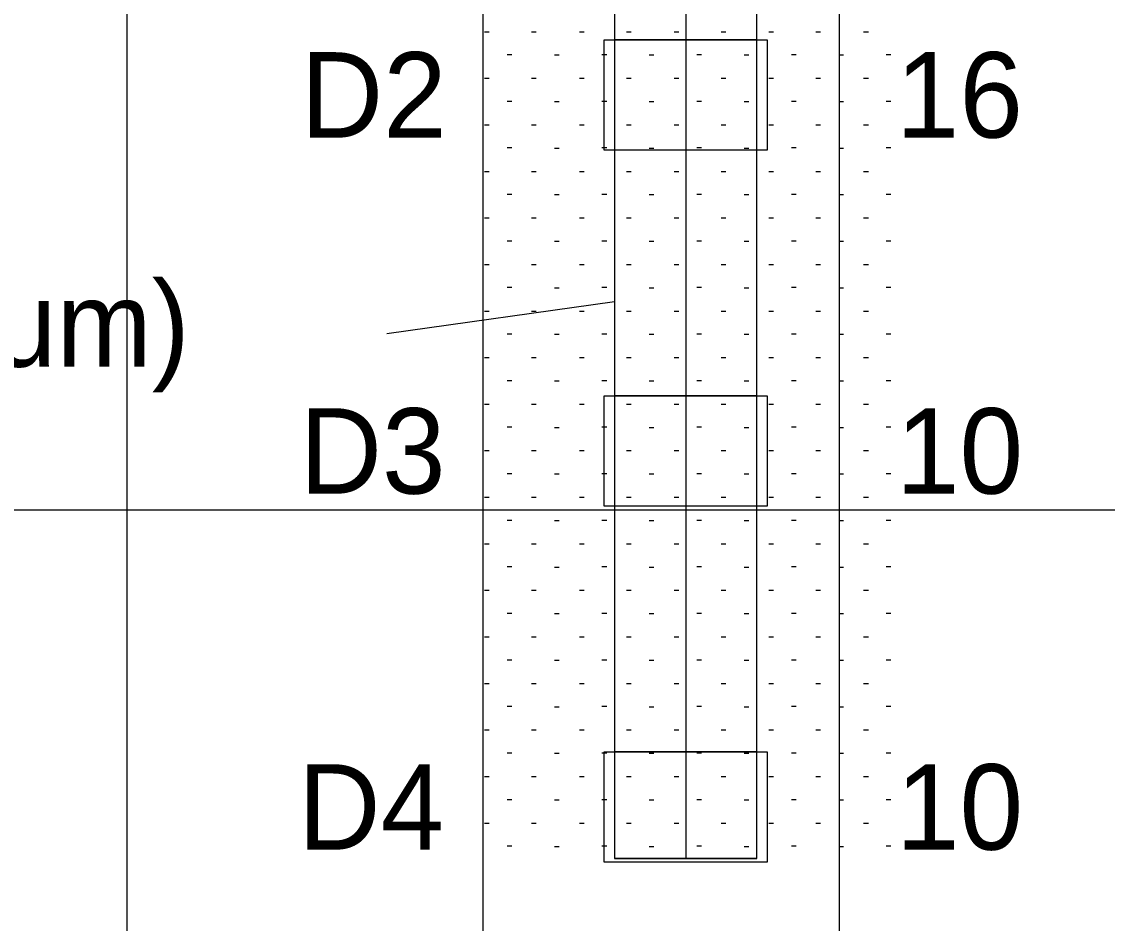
# Model space of a CAD drawing. Extents: x -290 to 297, y 616 to 861.
# Drawn here: x 137.04 to 167.52, y 678.38 to 703.71 of the extents above; entities that cross this region are included whole.
import ezdxf

# ---------------------------------------------------------------- set-up
doc = ezdxf.new("R2010")
doc.units = 0
for name, color, linetype in [('Default', 7, 'Continuous'), ('DisROW Proposed Temp Easements', 7, 'Continuous'), ('Draft_4', 7, 'Continuous'), ('SewerStormPipe', 7, 'Continuous'), ('TextAlignment', 7, 'Continuous'), ('TextAlignmentSml', 7, 'Continuous'), ('V-SWLK-CONC', 7, 'Continuous')]:
    doc.layers.add(name, color=color, linetype=linetype)

msp = doc.modelspace()

# ---------------------------------------------------------------- linework, layer by layer
at = {"layer": 'Default'}
for p, q in [((155.685, 741.2), (155.685, 680.2)), ((157.685, 680.2), (153.685, 680.2))]:
    msp.add_line(p, q, dxfattribs=at)
at = {"layer": 'DisROW Proposed Temp Easements'}
for points in [[(153.397, 703.2), (157.973, 703.2), (157.973, 700.104), (153.397, 700.104)], [(153.397, 693.2), (157.973, 693.2), (157.973, 690.104), (153.397, 690.104)], [(153.397, 683.2), (157.973, 683.2), (157.973, 680.104), (153.397, 680.104)]]:
    msp.add_lwpolyline(points, close=True, dxfattribs=at)
at = {"layer": 'Draft_4'}
msp.add_lwpolyline([(157.685, 717.2), (153.685, 717.2), (153.685, 680.2), (157.685, 680.2)], close=True, dxfattribs=at)
at = {"layer": 'SewerStormPipe'}
for p, q in [((157.685, 703.2), (153.685, 703.2)), ((157.685, 693.2), (153.685, 693.2)), ((157.685, 683.2), (153.685, 683.2))]:
    msp.add_line(p, q, dxfattribs=at)
at = {"layer": 'TextAlignment'}
for p, q in [((140, 630), (140, 787.989)), ((160, 630), (160, 787.989)), ((-275.612, 690), (284.208, 690))]:
    msp.add_line(p, q, dxfattribs=at)
at = {"layer": 'TextAlignmentSml'}
msp.add_line((150, 630), (150, 787.989), dxfattribs=at)
at = {"layer": 'V-SWLK-CONC'}
for p, q in [((150.038, 703.426), (150.17, 703.426)), ((151.358, 703.426), (151.49, 703.426)), ((152.699, 703.426), (152.831, 703.426)), ((154.019, 703.426), (154.151, 703.426)), ((155.36, 703.426), (155.492, 703.426)), ((156.68, 703.426), (156.812, 703.426)), ((158.021, 703.426), (158.153, 703.426)), ((159.341, 703.426), (159.473, 703.426)), ((160.682, 703.426), (160.814, 703.426)), ((150.673, 702.786), (150.805, 702.786)), ((152.002, 702.773), (152.134, 702.773)), ((153.334, 702.786), (153.466, 702.786)), ((154.663, 702.773), (154.795, 702.773)), ((155.995, 702.786), (156.127, 702.786)), ((157.324, 702.773), (157.456, 702.773)), ((158.656, 702.786), (158.788, 702.786)), ((159.985, 702.773), (160.117, 702.773)), ((161.317, 702.786), (161.449, 702.786)), ((150.038, 702.119), (150.17, 702.119)), ((151.358, 702.119), (151.49, 702.119)), ((152.699, 702.119), (152.831, 702.119)), ((154.019, 702.119), (154.151, 702.119)), ((155.36, 702.119), (155.492, 702.119)), ((156.68, 702.119), (156.812, 702.119)), ((158.021, 702.119), (158.153, 702.119)), ((159.341, 702.119), (159.473, 702.119)), ((160.682, 702.119), (160.814, 702.119)), ((150.673, 701.478), (150.805, 701.478)), ((152.002, 701.465), (152.134, 701.465)), ((153.334, 701.478), (153.466, 701.478)), ((154.663, 701.465), (154.795, 701.465)), ((155.995, 701.478), (156.127, 701.478)), ((157.324, 701.465), (157.456, 701.465)), ((158.656, 701.478), (158.788, 701.478)), ((159.985, 701.465), (160.117, 701.465)), ((161.317, 701.478), (161.449, 701.478)), ((150.038, 700.811), (150.17, 700.811)), ((151.358, 700.811), (151.49, 700.811)), ((152.699, 700.811), (152.831, 700.811)), ((154.019, 700.811), (154.151, 700.811)), ((155.36, 700.811), (155.492, 700.811)), ((156.68, 700.811), (156.812, 700.811)), ((158.021, 700.811), (158.153, 700.811)), ((159.341, 700.811), (159.473, 700.811)), ((160.682, 700.811), (160.814, 700.811)), ((150.673, 700.171), (150.805, 700.171)), ((152.002, 700.157), (152.134, 700.157)), ((153.334, 700.171), (153.466, 700.171)), ((154.663, 700.157), (154.795, 700.157)), ((155.995, 700.171), (156.127, 700.171)), ((157.324, 700.157), (157.456, 700.157)), ((158.656, 700.171), (158.788, 700.171)), ((159.985, 700.157), (160.117, 700.157)), ((161.317, 700.171), (161.449, 700.171)), ((150.038, 699.504), (150.17, 699.504)), ((151.358, 699.504), (151.49, 699.504)), ((152.699, 699.504), (152.831, 699.504)), ((154.019, 699.504), (154.151, 699.504)), ((155.36, 699.504), (155.492, 699.504)), ((156.68, 699.504), (156.812, 699.504)), ((158.021, 699.504), (158.153, 699.504)), ((159.341, 699.504), (159.473, 699.504)), ((160.682, 699.504), (160.814, 699.504)), ((150.673, 698.863), (150.805, 698.863)), ((152.002, 698.85), (152.134, 698.85)), ((153.334, 698.863), (153.466, 698.863)), ((154.663, 698.85), (154.795, 698.85)), ((155.995, 698.863), (156.127, 698.863)), ((157.324, 698.85), (157.456, 698.85)), ((158.656, 698.863), (158.788, 698.863)), ((159.985, 698.85), (160.117, 698.85)), ((161.317, 698.863), (161.449, 698.863)), ((150.038, 698.196), (150.17, 698.196)), ((151.358, 698.196), (151.49, 698.196)), ((152.699, 698.196), (152.831, 698.196)), ((154.019, 698.196), (154.151, 698.196)), ((155.36, 698.196), (155.492, 698.196)), ((156.68, 698.196), (156.812, 698.196)), ((158.021, 698.196), (158.153, 698.196)), ((159.341, 698.196), (159.473, 698.196)), ((160.682, 698.196), (160.814, 698.196)), ((150.673, 697.556), (150.805, 697.556)), ((152.002, 697.542), (152.134, 697.542)), ((153.334, 697.556), (153.466, 697.556)), ((154.663, 697.542), (154.795, 697.542)), ((155.995, 697.556), (156.127, 697.556)), ((157.324, 697.542), (157.456, 697.542)), ((158.656, 697.556), (158.788, 697.556)), ((159.985, 697.542), (160.117, 697.542)), ((161.317, 697.556), (161.449, 697.556)), ((150.038, 696.889), (150.17, 696.889)), ((151.358, 696.889), (151.49, 696.889)), ((152.699, 696.889), (152.831, 696.889)), ((154.019, 696.889), (154.151, 696.889)), ((155.36, 696.889), (155.492, 696.889)), ((156.68, 696.889), (156.812, 696.889)), ((158.021, 696.889), (158.153, 696.889)), ((159.341, 696.889), (159.473, 696.889)), ((160.682, 696.889), (160.814, 696.889)), ((150.673, 696.248), (150.805, 696.248)), ((152.002, 696.235), (152.134, 696.235)), ((153.334, 696.248), (153.466, 696.248)), ((154.663, 696.235), (154.795, 696.235)), ((155.995, 696.248), (156.127, 696.248)), ((157.324, 696.235), (157.456, 696.235)), ((158.656, 696.248), (158.788, 696.248)), ((159.985, 696.235), (160.117, 696.235)), ((161.317, 696.248), (161.449, 696.248)), ((153.685, 695.838), (147.295, 694.94)), ((150.038, 695.581), (150.17, 695.581)), ((151.358, 695.581), (151.49, 695.581)), ((152.699, 695.581), (152.831, 695.581)), ((154.019, 695.581), (154.151, 695.581)), ((155.36, 695.581), (155.492, 695.581)), ((156.68, 695.581), (156.812, 695.581)), ((158.021, 695.581), (158.153, 695.581)), ((159.341, 695.581), (159.473, 695.581)), ((160.682, 695.581), (160.814, 695.581)), ((150.673, 694.941), (150.805, 694.941)), ((152.002, 694.927), (152.134, 694.927)), ((153.334, 694.941), (153.466, 694.941)), ((154.663, 694.927), (154.795, 694.927)), ((155.995, 694.941), (156.127, 694.941)), ((157.324, 694.927), (157.456, 694.927)), ((158.656, 694.941), (158.788, 694.941)), ((159.985, 694.927), (160.117, 694.927)), ((161.317, 694.941), (161.449, 694.941)), ((150.038, 694.274), (150.17, 694.274)), ((151.358, 694.274), (151.49, 694.274)), ((152.699, 694.274), (152.831, 694.274)), ((154.019, 694.274), (154.151, 694.274)), ((155.36, 694.274), (155.492, 694.274)), ((156.68, 694.274), (156.812, 694.274)), ((158.021, 694.274), (158.153, 694.274)), ((159.341, 694.274), (159.473, 694.274)), ((160.682, 694.274), (160.814, 694.274)), ((150.673, 693.633), (150.805, 693.633)), ((152.002, 693.62), (152.134, 693.62)), ((153.334, 693.633), (153.466, 693.633)), ((154.663, 693.62), (154.795, 693.62)), ((155.995, 693.633), (156.127, 693.633)), ((157.324, 693.62), (157.456, 693.62)), ((158.656, 693.633), (158.788, 693.633)), ((159.985, 693.62), (160.117, 693.62)), ((161.317, 693.633), (161.449, 693.633)), ((150.038, 692.966), (150.17, 692.966)), ((151.358, 692.966), (151.49, 692.966)), ((152.699, 692.966), (152.831, 692.966)), ((154.019, 692.966), (154.151, 692.966)), ((155.36, 692.966), (155.492, 692.966)), ((156.68, 692.966), (156.812, 692.966)), ((158.021, 692.966), (158.153, 692.966)), ((159.341, 692.966), (159.473, 692.966)), ((160.682, 692.966), (160.814, 692.966)), ((150.673, 692.326), (150.805, 692.326)), ((152.002, 692.312), (152.134, 692.312)), ((153.334, 692.326), (153.466, 692.326)), ((154.663, 692.312), (154.795, 692.312)), ((155.995, 692.326), (156.127, 692.326)), ((157.324, 692.312), (157.456, 692.312)), ((158.656, 692.326), (158.788, 692.326)), ((159.985, 692.312), (160.117, 692.312)), ((161.317, 692.326), (161.449, 692.326)), ((150.038, 691.659), (150.17, 691.659)), ((151.358, 691.659), (151.49, 691.659)), ((152.699, 691.659), (152.831, 691.659)), ((154.019, 691.659), (154.151, 691.659)), ((155.36, 691.659), (155.492, 691.659)), ((156.68, 691.659), (156.812, 691.659)), ((158.021, 691.659), (158.153, 691.659)), ((159.341, 691.659), (159.473, 691.659)), ((160.682, 691.659), (160.814, 691.659)), ((150.673, 691.018), (150.805, 691.018)), ((152.002, 691.005), (152.134, 691.005)), ((153.334, 691.018), (153.466, 691.018)), ((154.663, 691.005), (154.795, 691.005)), ((155.995, 691.018), (156.127, 691.018)), ((157.324, 691.005), (157.456, 691.005)), ((158.656, 691.018), (158.788, 691.018)), ((159.985, 691.005), (160.117, 691.005)), ((161.317, 691.018), (161.449, 691.018)), ((150.038, 690.351), (150.17, 690.351)), ((151.358, 690.351), (151.49, 690.351)), ((152.699, 690.351), (152.831, 690.351)), ((154.019, 690.351), (154.151, 690.351)), ((155.36, 690.351), (155.492, 690.351)), ((156.68, 690.351), (156.812, 690.351)), ((158.021, 690.351), (158.153, 690.351)), ((159.341, 690.351), (159.473, 690.351)), ((160.682, 690.351), (160.814, 690.351)), ((150.673, 689.71), (150.805, 689.71)), ((152.002, 689.697), (152.134, 689.697)), ((153.334, 689.71), (153.466, 689.71)), ((154.663, 689.697), (154.795, 689.697)), ((155.995, 689.71), (156.127, 689.71)), ((157.324, 689.697), (157.456, 689.697)), ((158.656, 689.71), (158.788, 689.71)), ((159.985, 689.697), (160.117, 689.697)), ((161.317, 689.71), (161.449, 689.71)), ((150.038, 689.043), (150.17, 689.043)), ((151.358, 689.043), (151.49, 689.043)), ((152.699, 689.043), (152.831, 689.043)), ((154.019, 689.043), (154.151, 689.043)), ((155.36, 689.043), (155.492, 689.043)), ((156.68, 689.043), (156.812, 689.043)), ((158.021, 689.043), (158.153, 689.043)), ((159.341, 689.043), (159.473, 689.043)), ((160.682, 689.043), (160.814, 689.043)), ((150.673, 688.403), (150.805, 688.403)), ((152.002, 688.39), (152.134, 688.39)), ((153.334, 688.403), (153.466, 688.403)), ((154.663, 688.39), (154.795, 688.39)), ((155.995, 688.403), (156.127, 688.403)), ((157.324, 688.39), (157.456, 688.39)), ((158.656, 688.403), (158.788, 688.403)), ((159.985, 688.39), (160.117, 688.39)), ((161.317, 688.403), (161.449, 688.403)), ((150.038, 687.736), (150.17, 687.736)), ((151.358, 687.736), (151.49, 687.736)), ((152.699, 687.736), (152.831, 687.736)), ((154.019, 687.736), (154.151, 687.736)), ((155.36, 687.736), (155.492, 687.736)), ((156.68, 687.736), (156.812, 687.736)), ((158.021, 687.736), (158.153, 687.736)), ((159.341, 687.736), (159.473, 687.736)), ((160.682, 687.736), (160.814, 687.736)), ((150.673, 687.095), (150.805, 687.095)), ((152.002, 687.082), (152.134, 687.082)), ((153.334, 687.095), (153.466, 687.095)), ((154.663, 687.082), (154.795, 687.082)), ((155.995, 687.095), (156.127, 687.095)), ((157.324, 687.082), (157.456, 687.082)), ((158.656, 687.095), (158.788, 687.095)), ((159.985, 687.082), (160.117, 687.082)), ((161.317, 687.095), (161.449, 687.095)), ((150.038, 686.428), (150.17, 686.428)), ((151.358, 686.428), (151.49, 686.428)), ((152.699, 686.428), (152.831, 686.428)), ((154.019, 686.428), (154.151, 686.428)), ((155.36, 686.428), (155.492, 686.428)), ((156.68, 686.428), (156.812, 686.428)), ((158.021, 686.428), (158.153, 686.428)), ((159.341, 686.428), (159.473, 686.428)), ((160.682, 686.428), (160.814, 686.428)), ((150.673, 685.788), (150.805, 685.788)), ((152.002, 685.775), (152.134, 685.775)), ((153.334, 685.788), (153.466, 685.788)), ((154.663, 685.775), (154.795, 685.775)), ((155.995, 685.788), (156.127, 685.788)), ((157.324, 685.775), (157.456, 685.775)), ((158.656, 685.788), (158.788, 685.788)), ((159.985, 685.775), (160.117, 685.775)), ((161.317, 685.788), (161.449, 685.788)), ((150.038, 685.121), (150.17, 685.121)), ((151.358, 685.121), (151.49, 685.121)), ((152.699, 685.121), (152.831, 685.121)), ((154.019, 685.121), (154.151, 685.121)), ((155.36, 685.121), (155.492, 685.121)), ((156.68, 685.121), (156.812, 685.121)), ((158.021, 685.121), (158.153, 685.121)), ((159.341, 685.121), (159.473, 685.121)), ((160.682, 685.121), (160.814, 685.121)), ((150.673, 684.48), (150.805, 684.48)), ((152.002, 684.467), (152.134, 684.467)), ((153.334, 684.48), (153.466, 684.48)), ((154.663, 684.467), (154.795, 684.467)), ((155.995, 684.48), (156.127, 684.48)), ((157.324, 684.467), (157.456, 684.467)), ((158.656, 684.48), (158.788, 684.48)), ((159.985, 684.467), (160.117, 684.467)), ((161.317, 684.48), (161.449, 684.48)), ((150.038, 683.813), (150.17, 683.813)), ((151.358, 683.813), (151.49, 683.813)), ((152.699, 683.813), (152.831, 683.813)), ((154.019, 683.813), (154.151, 683.813)), ((155.36, 683.813), (155.492, 683.813)), ((156.68, 683.813), (156.812, 683.813)), ((158.021, 683.813), (158.153, 683.813)), ((159.341, 683.813), (159.473, 683.813)), ((160.682, 683.813), (160.814, 683.813)), ((150.673, 683.173), (150.805, 683.173)), ((152.002, 683.16), (152.134, 683.16)), ((153.334, 683.173), (153.466, 683.173)), ((154.663, 683.16), (154.795, 683.16)), ((155.995, 683.173), (156.127, 683.173)), ((157.324, 683.16), (157.456, 683.16)), ((158.656, 683.173), (158.788, 683.173)), ((159.985, 683.16), (160.117, 683.16)), ((161.317, 683.173), (161.449, 683.173)), ((150.038, 682.506), (150.17, 682.506)), ((151.358, 682.506), (151.49, 682.506)), ((152.699, 682.506), (152.831, 682.506)), ((154.019, 682.506), (154.151, 682.506)), ((155.36, 682.506), (155.492, 682.506)), ((156.68, 682.506), (156.812, 682.506)), ((158.021, 682.506), (158.153, 682.506)), ((159.341, 682.506), (159.473, 682.506)), ((160.682, 682.506), (160.814, 682.506)), ((150.673, 681.865), (150.805, 681.865)), ((152.002, 681.852), (152.134, 681.852)), ((153.334, 681.865), (153.466, 681.865)), ((154.663, 681.852), (154.795, 681.852)), ((155.995, 681.865), (156.127, 681.865)), ((157.324, 681.852), (157.456, 681.852)), ((158.656, 681.865), (158.788, 681.865)), ((159.985, 681.852), (160.117, 681.852)), ((161.317, 681.865), (161.449, 681.865)), ((150.038, 681.198), (150.17, 681.198)), ((151.358, 681.198), (151.49, 681.198)), ((152.699, 681.198), (152.831, 681.198)), ((154.019, 681.198), (154.151, 681.198)), ((155.36, 681.198), (155.492, 681.198)), ((156.68, 681.198), (156.812, 681.198)), ((158.021, 681.198), (158.153, 681.198)), ((159.341, 681.198), (159.473, 681.198)), ((160.682, 681.198), (160.814, 681.198)), ((150.673, 680.558), (150.805, 680.558)), ((152.002, 680.545), (152.134, 680.545)), ((153.334, 680.558), (153.466, 680.558)), ((154.663, 680.545), (154.795, 680.545)), ((155.995, 680.558), (156.127, 680.558)), ((157.324, 680.545), (157.456, 680.545)), ((158.656, 680.558), (158.788, 680.558)), ((159.985, 680.545), (160.117, 680.545)), ((161.317, 680.558), (161.449, 680.558))]:
    msp.add_line(p, q, dxfattribs=at)

# ---------------------------------------------------------------- texts
for s, p in [('D2', (144.872, 700.452)), ('16', (161.585, 700.452)), ('BROWN FINE TO MEDIUM SAND (Alluvium)', (77.038, 694.017)), ('D3', (144.84, 690.452)), ('10', (161.591, 690.452)), ('D4', (144.799, 680.452)), ('10', (161.591, 680.452))]:
    msp.add_text(s, height=2.4, dxfattribs=at).set_placement(p)

doc.saveas('drawing.dxf')
